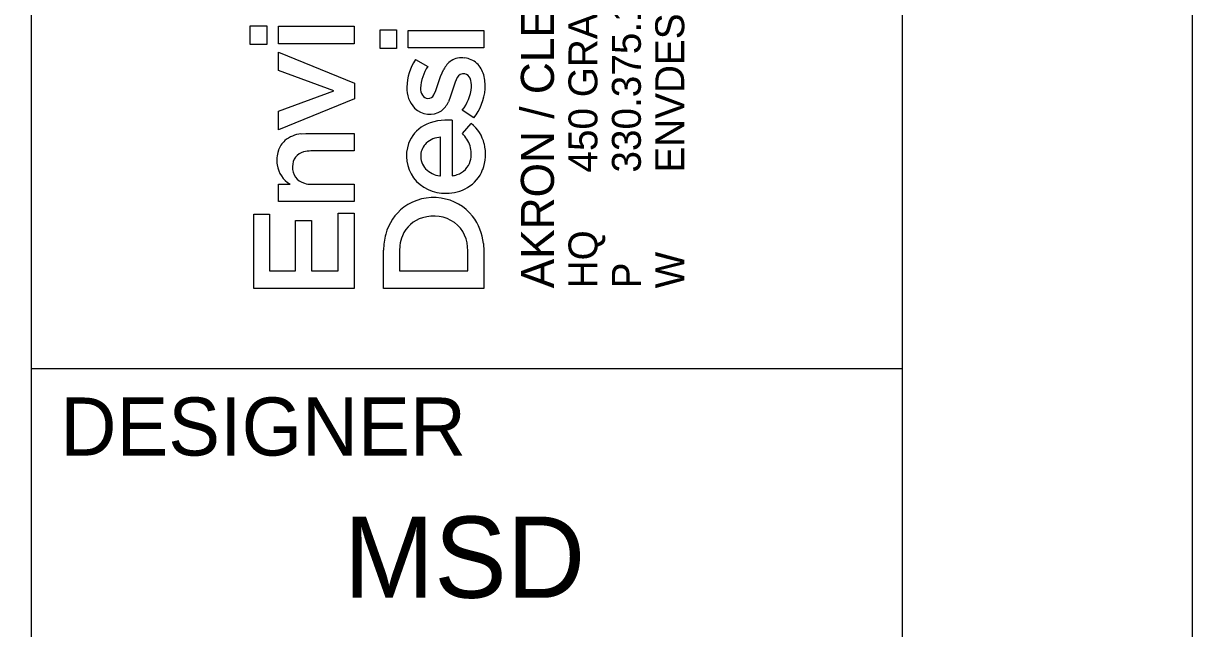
# Model space of a CAD drawing. Extents: x -0.2 to 34, y 0 to 22.
# Drawn here: x 31.986 to 34, y 2.552 to 3.594 of the extents above; entities that cross this region are included whole.
import ezdxf

# ---------------------------------------------------------------- set-up
doc = ezdxf.new("R2010")
doc.units = 0
for name, color, linetype in [('SH_Border', 7, 'Continuous'), ('SH_Cut_Line', 7, 'Continuous'), ('SH_Data', 7, 'Continuous')]:
    doc.layers.add(name, color=color, linetype=linetype)

msp = doc.modelspace()

# ---------------------------------------------------------------- linework, layer by layer
at = {"layer": 'SH_Border'}
for p, q in [((32, 0.5), (32, 21.5)), ((32, 3), (33.5, 3))]:
    msp.add_line(p, q, dxfattribs=at)
msp.add_lwpolyline([(1.5, 21.5), (33.5, 21.5), (33.5, 0.5), (1.5, 0.5)], close=True, dxfattribs=at)
at = {"layer": 'SH_Cut_Line'}
msp.add_lwpolyline([(0, 0), (34, 0), (34, 22), (0, 22)], close=True, dxfattribs=at)
at = {"layer": 'SH_Data'}
for p, q in [((32.3771, 3.5582), (32.3771, 3.5903)), ((32.3771, 3.5903), (32.4054, 3.5903)), ((32.4054, 3.5903), (32.4054, 3.5582)), ((32.4254, 3.5594), (32.4254, 3.5893)), ((32.4254, 3.5893), (32.5557, 3.5893)), ((32.5557, 3.5893), (32.5557, 3.5594)), ((32.6005, 3.5511), (32.6005, 3.5832)), ((32.6005, 3.5832), (32.6289, 3.5832)), ((32.6289, 3.5832), (32.6289, 3.5511)), ((32.6489, 3.5523), (32.6489, 3.5822)), ((32.6489, 3.5822), (32.7792, 3.5822)), ((32.7792, 3.5822), (32.7792, 3.5523)), ((32.4054, 3.5582), (32.3771, 3.5582)), ((32.5557, 3.5594), (32.4254, 3.5594)), ((32.4254, 3.5133), (32.4254, 3.5446)), ((32.4254, 3.5446), (32.5567, 3.4913)), ((32.6289, 3.5511), (32.6005, 3.5511)), ((32.7792, 3.5523), (32.6489, 3.5523)), ((32.6615, 3.5321), (32.6827, 3.5203)), ((32.5212, 3.478), (32.4254, 3.5133)), ((32.7048, 3.5026), (32.7104, 3.5153)), ((32.5567, 3.4913), (32.5567, 3.4644)), ((32.6967, 3.4787), (32.7048, 3.5026)), ((32.7298, 3.4933), (32.7221, 3.4688)), ((32.7334, 3.501), (32.7298, 3.4933)), ((32.4254, 3.4429), (32.5212, 3.478)), ((32.5567, 3.4644), (32.4254, 3.4109)), ((32.693, 3.4712), (32.6967, 3.4787)), ((32.7221, 3.4688), (32.7182, 3.4592)), ((32.7621, 3.4314), (32.742, 3.4447)), ((32.4254, 3.4109), (32.4254, 3.4429)), ((32.7245, 3.4275), (32.7246, 3.3319)), ((32.4644, 3.404), (32.4729, 3.4044)), ((32.4729, 3.4044), (32.5557, 3.4044)), ((32.5557, 3.4044), (32.5557, 3.3746)), ((32.7423, 3.4046), (32.7577, 3.422)), ((32.7049, 3.3318), (32.7049, 3.3983)), ((32.5557, 3.3746), (32.4814, 3.3746)), ((32.7036, 3.3317), (32.7049, 3.3318)), ((32.4254, 3.2875), (32.4254, 3.3173)), ((32.4254, 3.3173), (32.4455, 3.3173)), ((32.4822, 3.3173), (32.5557, 3.3173)), ((32.5557, 3.3173), (32.5557, 3.2876)), ((32.5557, 3.2876), (32.4254, 3.2875)), ((32.383, 3.1379), (32.383, 3.266)), ((32.383, 3.266), (32.4101, 3.266)), ((32.4101, 3.266), (32.4101, 3.1683)), ((32.5286, 3.1683), (32.5286, 3.2672)), ((32.5286, 3.2672), (32.5557, 3.2672)), ((32.5557, 3.2672), (32.5557, 3.1379)), ((32.455, 3.1683), (32.455, 3.2549)), ((32.455, 3.2549), (32.4822, 3.2549)), ((32.4822, 3.2549), (32.4822, 3.1683)), ((32.6064, 3.138), (32.6064, 3.204)), ((32.6347, 3.2118), (32.6341, 3.2023)), ((32.6341, 3.2023), (32.6341, 3.1684)), ((32.7515, 3.1683), (32.7515, 3.2024)), ((32.7785, 3.215), (32.7792, 3.2021)), ((32.7792, 3.2021), (32.7792, 3.138)), ((32.4101, 3.1683), (32.455, 3.1683)), ((32.4822, 3.1683), (32.5286, 3.1683)), ((32.6341, 3.1684), (32.7515, 3.1683)), ((32.5557, 3.1379), (32.383, 3.1379)), ((32.7792, 3.138), (32.6064, 3.138))]:
    msp.add_line(p, q, dxfattribs=at)
for points in [[(32.3771, 3.5582), (32.3771, 3.5903), (32.4054, 3.5903), (32.4054, 3.5582)], [(32.4254, 3.5594), (32.4254, 3.5893), (32.5557, 3.5893), (32.5557, 3.5594)], [(32.6005, 3.5511), (32.6005, 3.5832), (32.6289, 3.5832), (32.6289, 3.5511)], [(32.6489, 3.5523), (32.6489, 3.5822), (32.7792, 3.5822), (32.7792, 3.5523)], [(32.4254, 3.4109), (32.4254, 3.4429), (32.5212, 3.478), (32.4254, 3.5133), (32.4254, 3.5446), (32.5567, 3.4913), (32.5567, 3.4644)], [(32.383, 3.1379), (32.383, 3.266), (32.4101, 3.266), (32.4101, 3.1683), (32.455, 3.1683), (32.455, 3.2549), (32.4822, 3.2549), (32.4822, 3.1683), (32.5286, 3.1683), (32.5286, 3.2672), (32.5557, 3.2672), (32.5557, 3.1379)]]:
    msp.add_lwpolyline(points, close=True, dxfattribs=at)
for points in [[(32.6615, 3.5321), (32.6827, 3.5203)], [(32.693, 3.4712), (32.6967, 3.4787), (32.7048, 3.5026), (32.7104, 3.5153)], [(32.7334, 3.501), (32.7298, 3.4933), (32.7221, 3.4688), (32.7182, 3.4592)], [(32.7621, 3.4314), (32.742, 3.4447)], [(32.7245, 3.4275), (32.7246, 3.3319)], [(32.4644, 3.404), (32.4729, 3.4044), (32.5557, 3.4044), (32.5557, 3.3746), (32.4814, 3.3746)], [(32.7423, 3.4046), (32.7577, 3.422)], [(32.7036, 3.3317), (32.7049, 3.3318), (32.7049, 3.3983)], [(32.4254, 3.2875), (32.4254, 3.3173), (32.4455, 3.3173)], [(32.4822, 3.3173), (32.5557, 3.3173), (32.5557, 3.2876), (32.4254, 3.2875)], [(32.7785, 3.215), (32.7792, 3.2021), (32.7792, 3.138), (32.6064, 3.138)], [(32.6064, 3.138), (32.6064, 3.204)], [(32.6347, 3.2118), (32.6341, 3.2023), (32.6341, 3.1684), (32.7515, 3.1683), (32.7515, 3.2024)]]:
    msp.add_lwpolyline(points, dxfattribs=at)
for centre, radius, start, end in [((32.7364, 3.4826), 0.0897, 146.531, 178.7571), ((32.7364, 3.4826), 0.0897, 146.531, 178.7571), ((32.7466, 3.4971), 0.0405, 125.5118, 153.4159), ((32.7466, 3.4971), 0.0405, 125.5118, 153.4159), ((32.7406, 3.5026), 0.0326, 80.1719, 122.5197), ((32.7406, 3.5026), 0.0326, 80.1719, 122.5197), ((32.7428, 3.4982), 0.0367, 47.7934, 84.6892), ((32.7428, 3.4982), 0.0367, 47.7934, 84.6892), ((32.7379, 3.4946), 0.0427, 14.9966, 46.2063), ((32.7379, 3.4946), 0.0427, 14.9966, 46.2063), ((32.7452, 3.4789), 0.0749, 146.5112, 176.9101), ((32.7452, 3.4789), 0.0749, 146.5112, 176.9101), ((32.7438, 3.4963), 0.0114, 76.6609, 155.7053), ((32.7438, 3.4963), 0.0114, 76.6609, 155.7053), ((32.744, 3.4951), 0.0126, 21.5098, 78.5262), ((32.744, 3.4951), 0.0126, 21.5098, 78.5262), ((32.7104, 3.4867), 0.0712, 355.8306, 15.3914), ((32.7104, 3.4867), 0.0712, 355.8306, 15.3914), ((32.6967, 3.4824), 0.0501, 177.5366, 222.7932), ((32.6967, 3.4824), 0.0501, 177.5366, 222.7932), ((32.6825, 3.4915), 0.0757, 321.811, 354.7969), ((32.6825, 3.4915), 0.0757, 321.811, 354.7969), ((32.7259, 3.4877), 0.0321, 354.5726, 22.068), ((32.7259, 3.4877), 0.0321, 354.5726, 22.068), ((32.6931, 3.4823), 0.0228, 178.4747, 211.0868), ((32.6931, 3.4823), 0.0228, 178.4747, 211.0868), ((32.6833, 3.4767), 0.0115, 212.2368, 268.3777), ((32.6833, 3.4767), 0.0115, 212.2368, 268.3777), ((32.6834, 3.4759), 0.0107, 267.716, 333.7337), ((32.6834, 3.4759), 0.0107, 267.716, 333.7337), ((32.6895, 3.4882), 0.0922, 321.9777, 355.8738), ((32.6895, 3.4882), 0.0922, 321.9777, 355.8738), ((32.686, 3.4753), 0.0375, 225.9854, 302.4797), ((32.686, 3.4753), 0.0375, 225.9854, 302.4797), ((32.681, 3.4758), 0.0408, 308.0877, 335.9874), ((32.681, 3.4758), 0.0408, 308.0877, 335.9874), ((32.7152, 3.3441), 0.0838, 83.615, 118.2876), ((32.7152, 3.3441), 0.0838, 83.615, 118.2876), ((32.4687, 3.3543), 0.0499, 94.9696, 130.2225), ((32.4687, 3.3543), 0.0499, 94.9696, 130.2225), ((32.7024, 3.3691), 0.0558, 118.8308, 160.6244), ((32.7024, 3.3691), 0.0558, 118.8308, 160.6244), ((32.7038, 3.3656), 0.0549, 19.0357, 45.4406), ((32.7038, 3.3656), 0.0549, 19.0357, 45.4406), ((32.7174, 3.3717), 0.0644, 13.5336, 51.3615), ((32.7174, 3.3717), 0.0644, 13.5336, 51.3615), ((32.4635, 3.3626), 0.0402, 132.2219, 161.6818), ((32.4635, 3.3626), 0.0402, 132.2219, 161.6818), ((32.7104, 3.3661), 0.0644, 160.5201, 215.7831), ((32.7104, 3.3661), 0.0644, 160.5201, 215.7831), ((32.7005, 3.3663), 0.0298, 132.9851, 177.179), ((32.7005, 3.3663), 0.0298, 132.9851, 177.179), ((32.7079, 3.3561), 0.0424, 94.008, 130.8817), ((32.7079, 3.3561), 0.0424, 94.008, 130.8817), ((32.7107, 3.3697), 0.047, 344.6059, 17.007), ((32.7107, 3.3697), 0.047, 344.6059, 17.007), ((32.7064, 3.3692), 0.0758, 339.3542, 13.3785), ((32.7064, 3.3692), 0.0758, 339.3542, 13.3785), ((32.4787, 3.3582), 0.056, 162.2736, 187.7919), ((32.4787, 3.3582), 0.056, 162.2736, 187.7919), ((32.4748, 3.3487), 0.025, 103.6865, 182.2187), ((32.4748, 3.3487), 0.025, 103.6865, 182.2187), ((32.4811, 3.3286), 0.046, 89.6049, 105.3284), ((32.4811, 3.3286), 0.046, 89.6049, 105.3284), ((32.7017, 3.365), 0.0311, 175.0013, 223.283), ((32.7017, 3.365), 0.0311, 175.0013, 223.283), ((32.4703, 3.358), 0.0476, 188.962, 238.7037), ((32.4703, 3.358), 0.0476, 188.962, 238.7037), ((32.4773, 3.3456), 0.0276, 175.5854, 255.1439), ((32.4773, 3.3456), 0.0276, 175.5854, 255.1439), ((32.7089, 3.3736), 0.0423, 225.0619, 262.7974), ((32.7089, 3.3736), 0.0423, 225.0619, 262.7974), ((32.7224, 3.3671), 0.035, 288.0077, 343.5508), ((32.7224, 3.3671), 0.035, 288.0077, 343.5508), ((32.7125, 3.3705), 0.0687, 217.7452, 271.6543), ((32.7125, 3.3705), 0.0687, 217.7452, 271.6543), ((32.7247, 3.3522), 0.0202, 269.7003, 294.8711), ((32.7247, 3.3522), 0.0202, 269.7003, 294.8711), ((32.7189, 3.3652), 0.0626, 300.9427, 338.7323), ((32.7189, 3.3652), 0.0626, 300.9427, 338.7323), ((32.4818, 3.3595), 0.0422, 254.0916, 270.5284), ((32.4818, 3.3595), 0.0422, 254.0916, 270.5284), ((32.7155, 3.3724), 0.0706, 269.2048, 300.3341), ((32.7155, 3.3724), 0.0706, 269.2048, 300.3341), ((32.6923, 3.2079), 0.0864, 81.194, 125.9984), ((32.6923, 3.2079), 0.0864, 81.194, 125.9984), ((32.6946, 3.2113), 0.0827, 37.8521, 82.402), ((32.6946, 3.2113), 0.0827, 37.8521, 82.402), ((32.6939, 3.2089), 0.0865, 127.2362, 165.148), ((32.6939, 3.2089), 0.0865, 127.2362, 165.148), ((32.6928, 3.1986), 0.0639, 55.6727, 107.2093), ((32.6928, 3.1986), 0.0639, 55.6727, 107.2093), ((32.6889, 3.2078), 0.054, 106.1881, 157.3861), ((32.6889, 3.2078), 0.054, 106.1881, 157.3861), ((32.6929, 3.205), 0.0587, 357.4662, 52.2665), ((32.6929, 3.205), 0.0587, 357.4662, 52.2665), ((32.6859, 3.2057), 0.0931, 5.7333, 37.304), ((32.6859, 3.2057), 0.0931, 5.7333, 37.304), ((32.7143, 3.2028), 0.1078, 164.7861, 179.3704), ((32.7143, 3.2028), 0.1078, 164.7861, 179.3704), ((32.6983, 3.2039), 0.0641, 157.3571, 172.9275), ((32.6983, 3.2039), 0.0641, 157.3571, 172.9275)]:
    msp.add_arc(centre, radius, start, end, dxfattribs=at)

# ---------------------------------------------------------------- texts
for s, height, p in [('450 GRANT ST., AKRON, OH  44311', 0.049846, (32.9749, 3.3374)), ('AKRON / CLEVELAND / COLUMBUS', 0.056969, (32.9001, 3.138)), ('ENVDESIGNGROUP.COM', 0.049846, (33.1244, 3.3374)), ('330.375.1390', 0.049846, (33.0497, 3.3374)), ('HQ ', 0.04985, (32.9749, 3.138)), ('W', 0.0498, (33.1244, 3.138)), ('P', 0.0498, (33.0497, 3.138))]:
    msp.add_text(s, height=height, rotation=90, dxfattribs=at).set_placement(p)
for s, height, p in [('DESIGNER', 0.1, (32.05, 2.85)), ('MSD', 0.14, (32.5379, 2.605))]:
    msp.add_text(s, height=height, dxfattribs=at).set_placement(p)

doc.saveas('drawing.dxf')
